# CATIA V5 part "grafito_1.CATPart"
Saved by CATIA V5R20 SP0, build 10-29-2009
Part number: grafito_1
Revision: ANY
Definition: UNKNOWN
Nomenclature: grafito
Source: Unknown
Bounding box of the stored display mesh (mm): x -2.489 to 2.498, y 2.434 to 22.434, z -2.5 to 2.5
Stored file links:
  C:\Users\Utente\Desktop\IO LAVORO\3D X SITO CF\CUMSA\3D files SD\SD 4528\grafito_1.CATPart
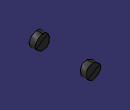
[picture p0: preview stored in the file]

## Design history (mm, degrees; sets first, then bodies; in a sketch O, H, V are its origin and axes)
Body1 "Saliente-Extruir1" (main body)
  Solid1: solid without history
Body2 "Saliente-Extruir1"
  Solid2: solid without history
